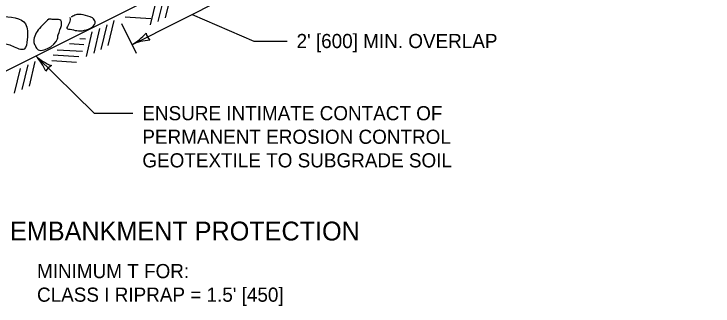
# Model space of a CAD drawing. Extents: x 49991.4 to 50021, y 49987.6 to 50011.4.
# Drawn here: x 50003.665 to 50006.635, y 50007.621 to 50008.86 of the extents above; entities that cross this region are included whole.
import ezdxf

# ---------------------------------------------------------------- set-up
doc = ezdxf.new("R2010")
doc.units = 0
for name, color, linetype in [('Level 1', 7, 'Continuous'), ('Level 2', 7, 'Continuous'), ('Level 3', 7, 'Continuous')]:
    doc.layers.add(name, color=color, linetype=linetype)

msp = doc.modelspace()

# ---------------------------------------------------------------- linework, layer by layer
at = {"layer": 'Level 1'}
for p, q in [((50003.3042, 50008.4558), (50006.7558, 50010.1815)), ((50004.3086, 50008.8442), (50004.3336, 50008.9489)), ((50004.2457, 50008.8141), (50004.2707, 50008.9188)), ((50004.2781, 50008.829), (50004.3031, 50008.9336)), ((50004.065, 50008.7273), (50004.09, 50008.8321)), ((50004.2461, 50008.8405), (50004.1368, 50008.8469)), ((50004.0052, 50008.6946), (50004.0302, 50008.7993)), ((50004.0357, 50008.7098), (50004.0607, 50008.8145)), ((50003.9728, 50008.6797), (50003.9978, 50008.7844)), ((50003.9625, 50008.73), (50003.9009, 50008.7336)), ((50003.9684, 50008.7542), (50003.9447, 50008.7555)), ((50003.9556, 50008.7011), (50003.8488, 50008.7075)), ((50003.9404, 50008.6788), (50003.8313, 50008.6855)), ((50003.7, 50008.5395), (50003.725, 50008.6442)), ((50003.7305, 50008.5548), (50003.7555, 50008.6594)), ((50003.9312, 50008.655), (50003.8255, 50008.6613)), ((50003.6676, 50008.5247), (50003.6926, 50008.6294))]:
    msp.add_line(p, q, dxfattribs=at)
for points in [[(50003.6037, 50008.8507), (50003.5322, 50008.7883), (50003.5552, 50008.736), (50003.5758, 50008.7179), (50003.6123, 50008.7308), (50003.6613, 50008.7222), (50003.7082, 50008.7113), (50003.7212, 50008.7524), (50003.7141, 50008.8179), (50003.6037, 50008.8507)], [(50003.9986, 50008.8438), (50003.9229, 50008.855), (50003.9074, 50008.8465)], [(50003.8137, 50008.8391), (50003.7685, 50008.7925), (50003.7501, 50008.739), (50003.7566, 50008.7239)], [(50003.8521, 50008.7714), (50003.8603, 50008.836), (50003.832, 50008.8374), (50003.8137, 50008.8391)], [(50003.9019, 50008.8449), (50003.9039, 50008.8352), (50003.8918, 50008.7976), (50003.9031, 50008.7965)], [(50003.9031, 50008.7965), (50003.9648, 50008.7911), (50004.0101, 50008.8266), (50003.9986, 50008.8438)], [(50003.7566, 50008.7239), (50003.7602, 50008.7155), (50003.8501, 50008.7555), (50003.8521, 50008.7714)]]:
    msp.add_spline(points, degree=3, dxfattribs=at)
at = {"layer": 'Level 3'}
for p, q in [((50004.1662, 50008.7302), (50004.6767, 50008.9876)), ((50004.1212, 50008.8195), (50004.1842, 50008.6945)), ((50003.7581, 50008.6827), (50004.0052, 50008.4395)), ((50004.0052, 50008.4395), (50004.1704, 50008.4395))]:
    msp.add_line(p, q, dxfattribs=at)
msp.add_lwpolyline([(50004.4214, 50008.8589), (50004.6836, 50008.7457), (50004.8256, 50008.7457)], dxfattribs=at)
for centre, radius, start, end in [((50004.0511, 50008.9328), 0.233, 299.5839, 318.8337), ((50004.2807, 50008.7879), 0.0548, 188.8954, 224.6177), ((50004.258, 50008.5277), 0.2223, 94.2126, 114.3961), ((50003.5957, 50008.5308), 0.2223, 22.9115, 43.095), ((50003.9131, 50008.8566), 0.233, 228.2828, 247.5326), ((50003.8495, 50008.5928), 0.0548, 117.5943, 153.3166)]:
    msp.add_arc(centre, radius, start, end, dxfattribs=at)

# ---------------------------------------------------------------- texts
at = {"layer": 'Level 2'}
for s, height, p in [("2' [600] MIN. OVERLAP", 0.06, (50004.8656, 50008.7157)), ('ENSURE INTIMATE CONTACT OF ', 0.06, (50004.2104, 50008.4095)), ('PERMANENT EROSION CONTROL', 0.06, (50004.2104, 50008.3095)), ('GEOTEXTILE TO SUBGRADE SOIL', 0.06, (50004.2104, 50008.2095)), ('EMBANKMENT PROTECTION', 0.08, (50003.6484, 50007.8995)), ('MINIMUM T FOR:', 0.06, (50003.763, 50007.7395)), ("CLASS I RIPRAP = 1.5' [450]", 0.06, (50003.763, 50007.6395))]:
    msp.add_text(s, height=height, dxfattribs=at).set_placement(p)

doc.saveas('drawing.dxf')
